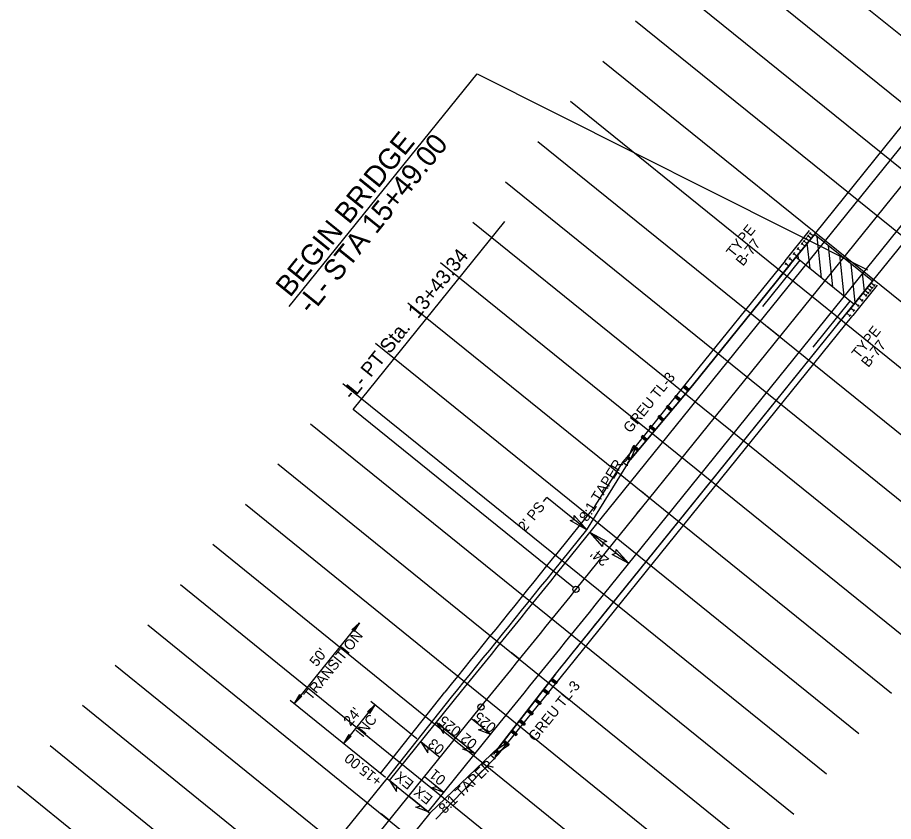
# Model space of a CAD drawing. Extents: x 2292992 to 2295123, y 892701 to 896230.
# Drawn here: x 2293417.1 to 2293840.1, y 893193.3 to 893581.3 of the extents above; entities that cross this region are included whole.
import ezdxf

# ---------------------------------------------------------------- set-up
doc = ezdxf.new("R2010")
doc.units = 0
for name, color, linetype in [('Prop Approach Slab', 7, 'Continuous'), ('Prop Approach Slab Hatching', 7, 'Continuous'), ('Prop Conc Shoulder Berm Gutter', 7, 'Continuous'), ('Prop Dimension', 7, 'Continuous'), ('Prop Dimension Text', 7, 'Continuous'), ('Prop EOT', 7, 'Continuous'), ('Prop Guardrail', 7, 'Continuous'), ('Prop Guardrail Anchor Unit CELL', 7, 'Continuous'), ('Prop Horizontal Alignment', 7, 'Continuous'), ('Prop Horizontal Alignment Station Label', 7, 'Continuous'), ('Prop Horizontal Alignment Tick Large', 7, 'Continuous'), ('Prop Horizontal Alignment Tick Small', 7, 'Continuous'), ('Prop Paved Shoulder', 7, 'Continuous'), ('Prop Roadway Bridge', 7, 'Continuous'), ('Prop SBG', 7, 'Continuous'), ('Prop Structure Anchor Unit CELL', 7, 'Continuous'), ('Prop Superelevation  Arrow CELL', 7, 'Continuous'), ('Prop Superelevation Label', 7, 'Continuous'), ('Prop Terminator CELL', 7, 'Continuous'), ('Scratch_Level_0', 7, 'Continuous'), ('Scratch_Level_1', 7, 'Continuous'), ('Scratch_Level_3', 7, 'Continuous'), ('Scratch_Level_4', 7, 'Continuous'), ('Scratch_Level_5', 7, 'Continuous'), ('Typical Terminator CELL', 7, 'Continuous')]:
    doc.layers.add(name, color=color, linetype=linetype)

# ---------------------------------------------------------------- blocks, each defined once
blk = doc.blocks.new('TERMINATOR')
at = {"layer": 'Typical Terminator CELL'}
blk.add_lwpolyline([(-0.469, 0.081), (0, 0), (-0.471, -0.083), (-0.411, 0)], close=True, dxfattribs=at)

msp = doc.modelspace()

# ---------------------------------------------------------------- linework, layer by layer
at = {"layer": 'Prop Approach Slab'}
for p, q in [((2293792.5, 893464.96), (2293801.93, 893476.63)), ((2293821.04, 893442.99), (2293793.03, 893465.6)), ((2293820.52, 893442.35), (2293829.94, 893454.02))]:
    msp.add_line(p, q, dxfattribs=at)
at = {"layer": 'Prop Approach Slab Hatching'}
for p, q in [((2293799.82, 893460.12), (2293798.51, 893472.39)), ((2293805.32, 893455.68), (2293803.2, 893475.6)), ((2293810.83, 893451.24), (2293808.7, 893471.16)), ((2293794.32, 893464.56), (2293794.07, 893466.88)), ((2293816.33, 893446.79), (2293814.2, 893466.72)), ((2293821.68, 893443.8), (2293819.7, 893462.28)), ((2293826.12, 893449.29), (2293825.21, 893457.84))]:
    msp.add_line(p, q, dxfattribs=at)
at = {"layer": 'Prop Conc Shoulder Berm Gutter'}
for p, q in [((2293785.14, 893455.82), (2293792.5, 893464.96)), ((2293813.14, 893433.2), (2293820.52, 893442.35))]:
    msp.add_line(p, q, dxfattribs=at)
at = {"layer": 'Prop Dimension'}
for p, q in [((2293671.13, 893347.71), (2293672.7, 893349.65)), ((2293692.01, 893334.06), (2293672.7, 893349.65)), ((2293712.25, 893317.74), (2293693.57, 893332.81)), ((2293550.8, 893250.26), (2293582.2, 893289.17)), ((2293548.84, 893251.81), (2293594.83, 893214.59)), ((2293574.64, 893230.93), (2293589.7, 893249.59)), ((2293609.94, 893233.17), (2293587.73, 893251.13))]:
    msp.add_line(p, q, dxfattribs=at)
at = {"layer": 'Prop Dimension Text'}
for p, q in [((2293548.3, 893441.78), (2293639.03, 893554.12)), ((2293639.03, 893554.12), (2293827.59, 893459.45))]:
    msp.add_line(p, q, dxfattribs=at)
at = {"layer": 'Prop EOT'}
for p, q in [((2293677.44, 893312.82), (2294149.49, 893897.76)), ((2293696.11, 893297.74), (2294168.17, 893882.69)), ((2293596.74, 893213.04), (2293631.58, 893256.08)), ((2293615.4, 893197.94), (2293650.24, 893240.98)), ((2293596.74, 893213.04), (2293615.4, 893197.94))]:
    msp.add_line(p, q, dxfattribs=at)
for points in [[(2293510.93, 893108.82), (2293514.29, 893112.95), (2293542.35, 893147.72), (2293569.63, 893181.99), (2293595.62, 893213.95)], [(2293531.53, 893092.15), (2293562.71, 893130.72), (2293590.2, 893164.83), (2293616.32, 893197.2)]]:
    msp.add_lwpolyline(points, dxfattribs=at)
for radius in [49988, 50012]:
    msp.add_arc((2254776.77, 924706.09), radius, 321.012472, 321.096083, dxfattribs=at)
at = {"layer": 'Prop Guardrail'}
for p, q in [((2293790.15, 893462.04), (2293743.05, 893403.67)), ((2293700.78, 893293.98), (2293818.17, 893439.43))]:
    msp.add_line(p, q, dxfattribs=at)
msp.add_arc((2254776.77, 924706.09), 50018, 321.052432, 321.096083, dxfattribs=at)
at = {"layer": 'Prop Guardrail Anchor Unit CELL'}
for p, q in [((2293743.05, 893403.67), (2293712.97, 893367.88)), ((2293739.12, 893403.66), (2293738.47, 893402.89)), ((2293740.77, 893400.96), (2293738.47, 893402.89)), ((2293738.47, 893402.89), (2293740.26, 893402.69)), ((2293741.41, 893401.73), (2293739.12, 893403.66)), ((2293739.62, 893401.93), (2293739.12, 893403.66)), ((2293740.26, 893402.69), (2293739.62, 893401.93)), ((2293740.77, 893400.96), (2293739.62, 893401.93)), ((2293739.62, 893401.93), (2293741.41, 893401.73)), ((2293740.26, 893402.69), (2293740.77, 893400.96)), ((2293741.41, 893401.73), (2293740.77, 893400.96)), ((2293735.02, 893398.87), (2293734.38, 893398.1)), ((2293736.71, 893396.14), (2293734.38, 893398.1)), ((2293734.38, 893398.1), (2293736.19, 893397.88)), ((2293737.36, 893396.9), (2293735.02, 893398.87)), ((2293735.55, 893397.12), (2293735.02, 893398.87)), ((2293736.19, 893397.88), (2293735.55, 893397.12)), ((2293737.36, 893396.9), (2293735.55, 893397.12)), ((2293736.19, 893397.88), (2293736.71, 893396.14)), ((2293730.97, 893394.04), (2293730.33, 893393.27)), ((2293732.66, 893391.31), (2293730.33, 893393.27)), ((2293730.33, 893393.27), (2293732.14, 893393.06)), ((2293733.3, 893392.08), (2293730.97, 893394.04)), ((2293731.49, 893392.29), (2293730.97, 893394.04)), ((2293732.14, 893393.06), (2293731.49, 893392.29)), ((2293733.3, 893392.08), (2293731.49, 893392.29)), ((2293732.14, 893393.06), (2293732.66, 893391.31)), ((2293726.93, 893389.21), (2293726.28, 893388.44)), ((2293728.61, 893386.49), (2293726.28, 893388.44)), ((2293726.28, 893388.44), (2293728.09, 893388.23)), ((2293729.25, 893387.26), (2293726.93, 893389.21)), ((2293727.44, 893387.47), (2293726.93, 893389.21)), ((2293728.09, 893388.23), (2293727.44, 893387.47)), ((2293729.25, 893387.26), (2293727.44, 893387.47)), ((2293728.09, 893388.23), (2293728.61, 893386.49)), ((2293729.25, 893387.26), (2293728.61, 893386.49)), ((2293722.79, 893384.45), (2293722.15, 893383.69)), ((2293724.55, 893381.67), (2293722.15, 893383.69)), ((2293722.15, 893383.69), (2293723.99, 893383.44)), ((2293725.19, 893382.43), (2293722.79, 893384.45)), ((2293723.35, 893382.68), (2293722.79, 893384.45)), ((2293723.99, 893383.44), (2293723.35, 893382.68)), ((2293723.99, 893383.44), (2293724.55, 893381.67)), ((2293718.84, 893379.54), (2293718.2, 893378.77)), ((2293720.5, 893376.84), (2293718.2, 893378.77)), ((2293718.2, 893378.77), (2293719.99, 893378.57)), ((2293721.14, 893377.61), (2293718.84, 893379.54)), ((2293719.35, 893377.81), (2293718.84, 893379.54)), ((2293719.99, 893378.57), (2293719.35, 893377.81)), ((2293719.99, 893378.57), (2293720.5, 893376.84)), ((2293725.19, 893382.43), (2293723.35, 893382.68)), ((2293714.74, 893374.76), (2293714.1, 893373.99)), ((2293717.09, 893372.78), (2293714.74, 893374.76)), ((2293715.27, 893373), (2293714.74, 893374.76)), ((2293721.14, 893377.61), (2293719.35, 893377.81)), ((2293714.1, 893373.99), (2293712.14, 893369.23)), ((2293715.27, 893373), (2293713.29, 893368.27)), ((2293716.44, 893372.02), (2293714.1, 893373.99)), ((2293714.1, 893373.99), (2293715.91, 893373.77)), ((2293715.91, 893373.77), (2293715.27, 893373)), ((2293717.09, 893372.78), (2293715.27, 893373)), ((2293715.91, 893373.77), (2293716.44, 893372.02)), ((2293709.24, 893366.71), (2293710.65, 893367.09)), ((2293711.53, 893364.86), (2293709.24, 893366.71)), ((2293710.65, 893367.09), (2293711.94, 893368.68)), ((2293712.14, 893369.23), (2293711.5, 893368.47)), ((2293712.64, 893367.5), (2293711.5, 893368.47)), ((2293711.5, 893368.47), (2293713.29, 893368.27)), ((2293711.6, 893366.32), (2293711.53, 893364.86)), ((2293712.89, 893367.91), (2293711.6, 893366.32)), ((2293712.14, 893369.23), (2293711.82, 893368.85)), ((2293711.94, 893368.68), (2293712.41, 893368.29)), ((2293713.29, 893368.27), (2293712.14, 893369.23)), ((2293712.64, 893367.5), (2293712.14, 893369.23)), ((2293712.41, 893368.29), (2293712.89, 893367.91)), ((2293676.84, 893264.33), (2293648.19, 893227.39)), ((2293675.28, 893262.32), (2293674.67, 893261.53)), ((2293674.67, 893261.53), (2293677.04, 893259.69)), ((2293674.67, 893261.53), (2293675.86, 893260.61)), ((2293676.47, 893261.4), (2293674.67, 893261.53)), ((2293675.28, 893262.32), (2293677.65, 893260.48)), ((2293675.86, 893260.61), (2293675.28, 893262.32)), ((2293676.47, 893261.4), (2293675.86, 893260.61)), ((2293675.86, 893260.61), (2293677.65, 893260.48)), ((2293677.04, 893259.69), (2293676.47, 893261.4)), ((2293677.65, 893260.48), (2293677.04, 893259.69)), ((2293670.81, 893256.55), (2293673.22, 893254.68)), ((2293672.63, 893256.41), (2293670.81, 893256.55)), ((2293671.42, 893257.34), (2293673.83, 893255.47)), ((2293671.42, 893257.34), (2293672.01, 893255.62)), ((2293672.63, 893256.41), (2293672.01, 893255.62)), ((2293673.22, 893254.68), (2293672.63, 893256.41)), ((2293667.56, 893252.36), (2293669.97, 893250.5)), ((2293667.56, 893252.36), (2293668.15, 893250.64)), ((2293672.01, 893255.62), (2293673.83, 893255.47)), ((2293673.83, 893255.47), (2293673.22, 893254.68)), ((2293663.7, 893247.39), (2293663.08, 893246.6)), ((2293663.7, 893247.39), (2293666.1, 893245.53)), ((2293663.7, 893247.39), (2293664.28, 893245.66)), ((2293666.95, 893251.57), (2293669.35, 893249.71)), ((2293668.76, 893251.43), (2293666.95, 893251.57)), ((2293668.76, 893251.43), (2293668.15, 893250.64)), ((2293668.15, 893250.64), (2293669.97, 893250.5)), ((2293669.35, 893249.71), (2293668.76, 893251.43)), ((2293669.97, 893250.5), (2293669.35, 893249.71)), ((2293663.08, 893246.6), (2293665.48, 893244.73)), ((2293664.9, 893246.45), (2293663.08, 893246.6)), ((2293664.9, 893246.45), (2293664.28, 893245.66)), ((2293664.28, 893245.66), (2293666.1, 893245.53)), ((2293665.48, 893244.73), (2293664.9, 893246.45)), ((2293666.1, 893245.53), (2293665.48, 893244.73)), ((2293659.22, 893241.62), (2293661.7, 893239.69)), ((2293661.08, 893241.45), (2293659.22, 893241.62)), ((2293659.84, 893242.41), (2293662.32, 893240.48)), ((2293659.84, 893242.41), (2293660.46, 893240.66)), ((2293661.08, 893241.45), (2293660.46, 893240.66)), ((2293660.46, 893240.66), (2293662.32, 893240.48)), ((2293661.7, 893239.69), (2293661.08, 893241.45)), ((2293662.32, 893240.48), (2293661.7, 893239.69)), ((2293655.36, 893236.64), (2293657.73, 893234.8)), ((2293657.16, 893236.51), (2293655.36, 893236.64)), ((2293655.97, 893237.43), (2293658.34, 893235.59)), ((2293655.97, 893237.43), (2293656.55, 893235.72)), ((2293657.16, 893236.51), (2293656.55, 893235.72)), ((2293656.55, 893235.72), (2293658.34, 893235.59)), ((2293657.73, 893234.8), (2293657.16, 893236.51)), ((2293658.34, 893235.59), (2293657.73, 893234.8)), ((2293652.71, 893230.72), (2293648.5, 893227.79)), ((2293651.5, 893231.66), (2293653.92, 893229.78)), ((2293653.32, 893231.51), (2293651.5, 893231.66)), ((2293652.11, 893232.45), (2293654.53, 893230.57)), ((2293652.11, 893232.45), (2293652.71, 893230.72)), ((2293653.32, 893231.51), (2293652.71, 893230.72)), ((2293652.71, 893230.72), (2293654.53, 893230.57)), ((2293653.92, 893229.78), (2293653.32, 893231.51)), ((2293654.53, 893230.57), (2293653.92, 893229.78)), ((2293648.23, 893227.32), (2293646.94, 893225.72)), ((2293647.88, 893226.99), (2293649.07, 893226.08)), ((2293647.88, 893226.99), (2293649.68, 893226.87)), ((2293647.9, 893224.96), (2293649.18, 893226.55)), ((2293648.7, 893226.94), (2293648.23, 893227.32)), ((2293648.5, 893227.79), (2293649.68, 893226.87)), ((2293649.07, 893226.08), (2293648.5, 893227.79)), ((2293649.18, 893226.55), (2293648.7, 893226.94)), ((2293649.68, 893226.87), (2293649.07, 893226.08)), ((2293649.68, 893226.87), (2293649.37, 893226.47)), ((2293653.92, 893229.78), (2293649.68, 893226.87)), ((2293646.94, 893225.72), (2293645.54, 893225.35)), ((2293645.54, 893225.35), (2293647.83, 893223.5)), ((2293647.83, 893223.5), (2293647.9, 893224.96))]:
    msp.add_line(p, q, dxfattribs=at)
at = {"layer": 'Prop Horizontal Alignment'}
for p, q in [((2293686.78, 893305.28), (2294292.7, 894056.1)), ((2293470.8, 893038.37), (2293640.91, 893248.53))]:
    msp.add_line(p, q, dxfattribs=at)
msp.add_arc((2254776.77, 924706.09), 50000, 321.012472, 321.096083, dxfattribs=at)
at = {"layer": 'Prop Horizontal Alignment Station Label'}
for p, q in [((2293579.19, 893392.1), (2293652.45, 893482.82)), ((2293685.61, 893306.22), (2293579.19, 893392.1))]:
    msp.add_line(p, q, dxfattribs=at)
for centre in [(2293686.78, 893305.28), (2293640.91, 893248.53)]:
    msp.add_circle(centre, 1.5, dxfattribs=at)
at = {"layer": 'Prop Horizontal Alignment Tick Large'}
msp.add_line((2293785.16, 893427.19), (2293778.93, 893432.22), dxfattribs=at)
at = {"layer": 'Prop Horizontal Alignment Tick Small'}
for p, q in [((2293722.36, 893349.37), (2293718.47, 893352.51)), ((2293659.54, 893271.56), (2293655.65, 893274.71)), ((2293596.63, 893193.83), (2293592.75, 893196.98))]:
    msp.add_line(p, q, dxfattribs=at)
at = {"layer": 'Prop Paved Shoulder'}
for p, q in [((2293790.16, 893462.03), (2293792.51, 893464.95)), ((2293743.05, 893403.67), (2293790.15, 893462.04)), ((2293700.78, 893293.98), (2293818.17, 893439.43)), ((2293743.05, 893403.67), (2293712.97, 893367.88)), ((2293692.01, 893334.06), (2293712.97, 893367.88)), ((2293675.88, 893314.07), (2293692.01, 893334.06)), ((2293676.84, 893264.33), (2293700.78, 893293.98)), ((2293649.69, 893229.33), (2293676.84, 893264.33)), ((2293595.61, 893213.96), (2293626.66, 893253.18)), ((2293649.69, 893229.33), (2293616.3, 893197.21)), ((2293595.61, 893213.96), (2293596.74, 893213.04)), ((2293615.4, 893197.94), (2293616.3, 893197.21))]:
    msp.add_line(p, q, dxfattribs=at)
msp.add_arc((2254776.77, 924706.09), 49986, 321.006338, 321.096083, dxfattribs=at)
at = {"layer": 'Prop Roadway Bridge'}
for p, q in [((2293801.93, 893476.63), (2293933.81, 893640.05)), ((2293829.94, 893454.02), (2293961.82, 893617.44)), ((2293829.94, 893454.02), (2293801.93, 893476.63))]:
    msp.add_line(p, q, dxfattribs=at)
at = {"layer": 'Prop SBG'}
for p, q in [((2293794.86, 893464.12), (2293776.9, 893441.89)), ((2293801.28, 893422.22), (2293819.23, 893444.46))]:
    msp.add_line(p, q, dxfattribs=at)
at = {"layer": 'Prop Structure Anchor Unit CELL'}
for p, q in [((2293801.93, 893476.63), (2293787.56, 893458.83)), ((2293799.12, 893476.34), (2293798.4, 893475.44)), ((2293800.32, 893474.63), (2293798.76, 893475.89)), ((2293800.1, 893477.55), (2293799.38, 893476.66)), ((2293801.3, 893475.85), (2293799.74, 893477.11)), ((2293796.18, 893472.69), (2293795.46, 893471.8)), ((2293797.37, 893470.99), (2293795.82, 893472.24)), ((2293797.16, 893473.9), (2293796.44, 893473.01)), ((2293798.35, 893472.2), (2293796.8, 893473.46)), ((2293798.14, 893475.12), (2293797.42, 893474.23)), ((2293799.33, 893473.42), (2293797.78, 893474.67)), ((2293792.25, 893467.82), (2293791.53, 893466.93)), ((2293793.45, 893466.12), (2293791.89, 893467.38)), ((2293794.21, 893470.26), (2293793.49, 893469.36)), ((2293795.41, 893468.55), (2293793.85, 893469.81)), ((2293790.29, 893465.39), (2293789.57, 893464.5)), ((2293791.48, 893463.69), (2293789.93, 893464.95)), ((2293788.33, 893462.96), (2293787.61, 893462.07)), ((2293789.52, 893461.26), (2293787.97, 893462.51)), ((2293829.94, 893454.02), (2293815.57, 893436.22)), ((2293827.35, 893450.81), (2293828.91, 893449.55)), ((2293828.33, 893452.03), (2293829.89, 893450.77)), ((2293829.31, 893453.24), (2293830.87, 893451.99)), ((2293830.25, 893451.22), (2293829.53, 893450.32)), ((2293831.23, 893452.43), (2293830.51, 893451.54)), ((2293825.39, 893448.38), (2293826.94, 893447.12)), ((2293826.37, 893449.59), (2293827.92, 893448.34)), ((2293827.3, 893447.57), (2293826.58, 893446.68)), ((2293828.28, 893448.78), (2293827.57, 893447.89)), ((2293829.27, 893450), (2293828.55, 893449.11)), ((2293821.46, 893443.51), (2293823.02, 893442.26)), ((2293823.38, 893442.7), (2293822.66, 893441.81)), ((2293823.42, 893445.95), (2293824.98, 893444.69)), ((2293825.34, 893445.14), (2293824.62, 893444.24)), ((2293817.54, 893438.65), (2293819.09, 893437.39)), ((2293819.45, 893437.84), (2293818.73, 893436.95)), ((2293819.5, 893441.08), (2293821.06, 893439.83)), ((2293821.42, 893440.27), (2293820.7, 893439.38))]:
    msp.add_line(p, q, dxfattribs=at)
at = {"layer": 'Prop Superelevation  Arrow CELL'}
for p, q in [((2293619.39, 893241.03), (2293628.72, 893233.49)), ((2293645.63, 893235.24), (2293636.3, 893242.78)), ((2293611.84, 893231.69), (2293621.18, 893224.15)), ((2293638.08, 893225.92), (2293628.75, 893233.46)), ((2293622.96, 893207.27), (2293613.63, 893214.82)), ((2293596.74, 893213.04), (2293606.08, 893205.5)), ((2293615.4, 893197.95), (2293606.07, 893205.49))]:
    msp.add_line(p, q, dxfattribs=at)
for points in [[(2293619.39, 893241.03), (2293622.8, 893235.7), (2293622.98, 893238.12)], [(2293645.63, 893235.24), (2293639.71, 893237.46), (2293642.04, 893238.15)], [(2293611.84, 893231.69), (2293615.25, 893226.37), (2293615.44, 893228.79)], [(2293638.08, 893225.92), (2293632.15, 893228.13), (2293634.48, 893228.83)], [(2293596.74, 893213.04), (2293600.15, 893207.71), (2293600.34, 893210.13)], [(2293622.96, 893207.27), (2293617.04, 893209.49), (2293619.37, 893210.18)], [(2293615.4, 893197.95), (2293609.48, 893200.17), (2293611.81, 893200.86)]]:
    msp.add_lwpolyline(points, close=True, dxfattribs=at)
at = {"layer": 'Prop Terminator CELL'}
for points in [[(2293685.98, 893340.92), (2293692.01, 893334.06), (2293683.97, 893338.5), (2293685.87, 893339.02)], [(2293699.6, 893325.95), (2293693.57, 893332.81), (2293701.62, 893328.37), (2293699.72, 893327.85)], [(2293706.21, 893324.6), (2293712.24, 893317.74), (2293704.2, 893322.18), (2293706.1, 893322.7)]]:
    msp.add_lwpolyline(points, close=True, dxfattribs=at)
at = {"layer": 'Scratch_Level_0'}
for p, q in [((2293787.81, 893463.93), (2293799.58, 893478.52)), ((2293787.81, 893463.93), (2293740.71, 893405.56)), ((2293832.28, 893452.13), (2293820.51, 893437.54)), ((2293679.18, 893262.45), (2293820.51, 893437.54)), ((2293711.44, 893369.17), (2293740.74, 893405.61)), ((2293696.14, 893345.54), (2293709.56, 893366.83)), ((2293709.56, 893366.83), (2293711.44, 893369.17)), ((2293696.14, 893345.54), (2293676.95, 893321.77)), ((2293716.42, 893342.02), (2293718.31, 893344.35)), ((2293672.77, 893316.59), (2293676.95, 893321.77)), ((2293649.42, 893225.8), (2293679.21, 893262.49)), ((2293592.47, 893216.44), (2293623.53, 893255.67)), ((2293649.42, 893225.8), (2293619.07, 893194.33))]:
    msp.add_line(p, q, dxfattribs=at)
msp.add_arc((2254776.77, 924706.09), 49982, 321.006338, 321.096083, dxfattribs=at)
at = {"layer": 'Scratch_Level_1'}
msp.add_line((2293628.72, 893233.49), (2293619.39, 893241.03), dxfattribs=at)
at = {"layer": 'Scratch_Level_3'}
for p, q in [((2293686.78, 893305.28), (2294292.7, 894056.1)), ((2293470.8, 893038.37), (2293640.91, 893248.53))]:
    msp.add_line(p, q, dxfattribs=at)
msp.add_arc((2254776.77, 924706.09), 50000, 321.012472, 321.096083, dxfattribs=at)
at = {"layer": 'Scratch_Level_4'}
for p, q in [((2293762.63, 893638.12), (2293996.09, 893449.72)), ((2293746.93, 893618.67), (2293980.39, 893430.26)), ((2293731.23, 893599.21), (2293964.69, 893410.81)), ((2293715.53, 893579.76), (2293948.99, 893391.35)), ((2293699.83, 893560.3), (2293933.29, 893371.9)), ((2293684.13, 893540.85), (2293917.59, 893352.44)), ((2293668.43, 893521.39), (2293901.89, 893332.99)), ((2293652.73, 893501.94), (2293886.19, 893313.53)), ((2293637.03, 893482.48), (2293870.49, 893294.08)), ((2293621.33, 893463.03), (2293854.79, 893274.62)), ((2293605.63, 893443.57), (2293839.09, 893255.17)), ((2293589.93, 893424.12), (2293823.39, 893235.71)), ((2293574.23, 893404.66), (2293807.69, 893216.26)), ((2293558.56, 893385.25), (2293791.95, 893196.76)), ((2293542.89, 893365.87), (2293776.19, 893177.26)), ((2293527.22, 893346.49), (2293760.42, 893157.76)), ((2293511.5, 893327.07), (2293744.68, 893138.32)), ((2293495.77, 893307.63), (2293728.96, 893118.89)), ((2293480.04, 893288.2), (2293713.23, 893099.46)), ((2293464.31, 893268.77), (2293697.5, 893080.03)), ((2293448.58, 893249.34), (2293681.77, 893060.59)), ((2293432.85, 893229.91), (2293666.04, 893041.16)), ((2293417.13, 893210.47), (2293650.31, 893021.73))]:
    msp.add_line(p, q, dxfattribs=at)
at = {"layer": 'Scratch_Level_5'}
for p, q in [((2293790.14, 893462.04), (2293801.92, 893476.63)), ((2293790.14, 893462.04), (2293743.04, 893403.68)), ((2293829.95, 893454.01), (2293818.17, 893439.42)), ((2293676.84, 893264.33), (2293818.17, 893439.42)), ((2293712.96, 893367.89), (2293743.04, 893403.68)), ((2293648.21, 893227.37), (2293676.84, 893264.33))]:
    msp.add_line(p, q, dxfattribs=at)

# ---------------------------------------------------------------- block references
at = {"layer": 'Prop Dimension', "xscale": 10.604453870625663, "yscale": 7.610350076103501}
for p, rotation in [((2293589.7, 893249.59), 51.09608270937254), ((2293574.64, 893230.93), -128.90391729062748)]:
    msp.add_blockref('TERMINATOR', p, dxfattribs=dict(at, rotation=rotation))
at = {"layer": 'Prop Dimension Text', "xscale": 10.604453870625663, "yscale": 7.610350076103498}
for p, rotation in [((2293582.2, 893289.17), 51.09608270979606), ((2293550.8, 893250.26), -128.90391729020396)]:
    msp.add_blockref('TERMINATOR', p, dxfattribs=dict(at, rotation=rotation))

# ---------------------------------------------------------------- texts
at = {"layer": 'Prop Dimension'}
msp.add_text("24'", height=5, rotation=51.0961, dxfattribs=at).set_placement((2293577.9, 893238.95))
at = {"layer": 'Prop Dimension Text'}
for s, height, rotation, p in [('BEGIN BRIDGE', 10, 51.0748, (2293548.75, 893445.83)), ('-L- STA 15+49.00', 10, 51.0748, (2293558.95, 893437.59)), ('8:1 TAPER', 5, 58.2212, (2293692.2, 893337.59)), ("2' PS", 5, 51.0748, (2293662.22, 893332.78)), ("24'", 5, 141.0961, (2293703.15, 893319.86)), ('TRANSITION', 5, 51.0961, (2293558.8, 893251.46)), ("50'", 5, 51.0961, (2293561.57, 893267.59)), ('INC', 5, 51.0961, (2293583.8, 893233.49)), ('+15.00', 5, 141.0961, (2293593.66, 893213.73)), ('8:1 TAPER', 5, 43.8874, (2293623.36, 893196.68))]:
    msp.add_text(s, height=height, rotation=rotation, dxfattribs=at).set_placement(p)
at = {"layer": 'Prop Guardrail Anchor Unit CELL'}
for p in [(2293713.07, 893380.4), (2293667.18, 893231.47)]:
    msp.add_text('GREU TL-3', height=5, rotation=51.0961, dxfattribs=at).set_placement(p)
at = {"layer": 'Prop Horizontal Alignment Station Label'}
msp.add_text('-L- PT Sta.  13+43.34', height=7, rotation=51.0748, dxfattribs=at).set_placement((2293578.83, 893396.3))
at = {"layer": 'Prop Structure Anchor Unit CELL'}
for s, p in [('TYPE', (2293762.8, 893465.21)), ('B-77', (2293767.41, 893460.98)), ('TYPE', (2293823.34, 893416.31)), ('B-77', (2293827.96, 893412.08))]:
    msp.add_text(s, height=5, rotation=51.0961, dxfattribs=at).set_placement(p)
at = {"layer": 'Prop Superelevation Label'}
for s, p in [('025', (2293631.8, 893237.7)), ('025', (2293648.73, 893239.54)), ('02', (2293639.51, 893231.67)), ('03', (2293623.72, 893229)), ('01', (2293624.41, 893214.18)), ('EX', (2293608.91, 893212.14)), ('EX', (2293618.08, 893204.94))]:
    msp.add_text(s, height=5, rotation=141.0961, dxfattribs=at).set_placement(p)

doc.saveas('drawing.dxf')
